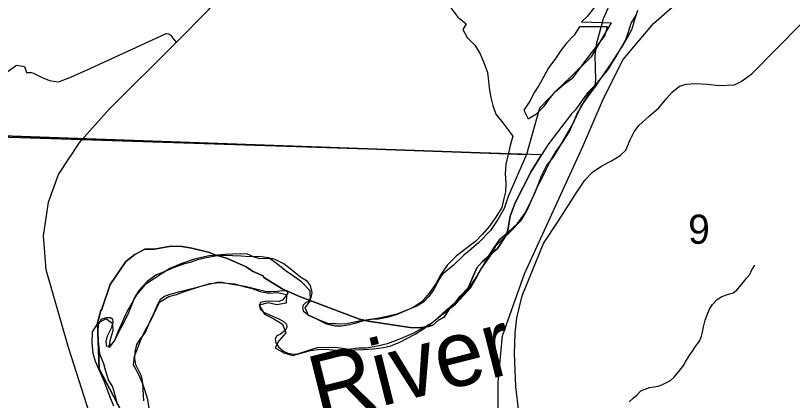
# Model space of a CAD drawing. Extents: x 0 to 34, y 0 to 22.
# Drawn here: x 3.401 to 4.521, y 19.391 to 19.945 of the extents above; entities that cross this region are included whole.
import ezdxf

# ---------------------------------------------------------------- set-up
doc = ezdxf.new("R2010")
doc.units = 0
for name, color, linetype in [('GM_X_County_Road', 7, 'Continuous'), ('GM_X_Major_River', 7, 'Continuous'), ('GM_X_Major_River_Text', 7, 'Continuous'), ('GM_X_Minor_River', 7, 'Continuous'), ('GM_X_Rail_Line', 7, 'Continuous'), ('GM_X_Section', 7, 'Continuous'), ('GM_X_Section_Text', 7, 'Continuous'), ('GM_X_State_Route', 7, 'Continuous')]:
    doc.layers.add(name, color=color, linetype=linetype)

msp = doc.modelspace()

# ---------------------------------------------------------------- linework, layer by layer
at = {"layer": 'GM_X_County_Road'}
for points in [[(4.1269, 19.3743), (4.1228, 19.4109), (4.1209, 19.4585), (4.1215, 19.4873), (4.1241, 19.5096), (4.1316, 19.5414), (4.1625, 19.6168), (4.1831, 19.648), (4.1986, 19.6722), (4.2087, 19.6877), (4.2222, 19.7082), (4.2333, 19.7195), (4.2467, 19.7285), (4.2605, 19.7358), (4.2728, 19.7436), (4.2811, 19.7514), (4.2876, 19.7662), (4.2934, 19.7777), (4.2999, 19.7869), (4.3149, 19.8001), (4.3287, 19.8121), (4.3404, 19.8258), (4.3481, 19.8347), (4.3586, 19.8432), (4.3683, 19.8464), (4.3814, 19.8472), (4.3986, 19.8461), (4.416, 19.8442), (4.4377, 19.8451), (4.4476, 19.85), (4.4628, 19.8611), (4.5336, 19.9326)], [(3.4971, 19.8633), (3.5036, 19.8663), (3.6177, 19.9188), (3.6193, 19.919), (3.6214, 19.9187), (3.6231, 19.9181), (3.6241, 19.9176), (3.6249, 19.9168), (3.6332, 19.9061)], [(3.3827, 19.8589), (3.403, 19.8734), (3.4146, 19.8714), (3.4172, 19.8628), (3.42, 19.863), (3.424, 19.863), (3.4275, 19.862), (3.4397, 19.8556), (3.4506, 19.8514), (3.4625, 19.8497), (3.4646, 19.8498), (3.4822, 19.8565), (3.4971, 19.8633)]]:
    msp.add_lwpolyline(points, dxfattribs=at)
at = {"layer": 'GM_X_Major_River'}
msp.add_line((4.2548, 19.9289), (4.2143, 19.9287), dxfattribs=at)
for points in [[(4.052, 20.1082), (4.0423, 20.1002), (4.0328, 20.1012), (4.0242, 20.0907), (4.0344, 20.0703), (4.0413, 20.0588), (4.0338, 20.0456), (4.027, 20.0325), (4.0207, 20.0186), (4.0136, 20.0085), (4.0167, 19.9966), (4.0214, 19.9828), (4.0245, 19.969), (4.0287, 19.956), (4.0391, 19.9425), (4.0508, 19.9329)], [(4.2901, 19.9259), (4.2942, 19.9394), (4.2986, 19.9526)], [(3.594, 19.3794), (3.5922, 19.392), (3.588, 19.4062), (3.5845, 19.4158), (3.5789, 19.4289), (3.5713, 19.4421), (3.5728, 19.4546), (3.5778, 19.4666), (3.5819, 19.4782), (3.588, 19.4906), (3.5969, 19.507), (3.6091, 19.5325), (3.6222, 19.5404), (3.6337, 19.5435), (3.6437, 19.5474), (3.6552, 19.5512), (3.6717, 19.5564), (3.6813, 19.5591), (3.6958, 19.5606), (3.7064, 19.5598), (3.717, 19.5588), (3.7305, 19.5549), (3.7426, 19.5519), (3.7542, 19.5477), (3.7667, 19.5454), (3.7792, 19.5462), (3.7921, 19.5435), (3.7917, 19.531), (3.7783, 19.5287), (3.7655, 19.5314), (3.7528, 19.528), (3.7604, 19.5152), (3.7739, 19.5084), (3.7862, 19.5007), (3.7911, 19.4881), (3.7809, 19.4766), (3.7756, 19.4665), (3.7883, 19.4593), (3.8011, 19.4554), (3.8145, 19.4592), (3.8268, 19.463), (3.8405, 19.4645), (3.8534, 19.4641), (3.8685, 19.4629), (3.8784, 19.4633), (3.8906, 19.4637), (3.9035, 19.464), (3.9176, 19.4651), (3.9317, 19.467), (3.9424, 19.4693), (3.9555, 19.475), (3.9655, 19.48), (3.9775, 19.4861), (3.9895, 19.4941), (3.9992, 19.5006), (4.0097, 19.5094), (4.0226, 19.5212), (4.0332, 19.5299), (4.0469, 19.5432), (4.0567, 19.5551), (4.0663, 19.5692), (4.0747, 19.5834), (4.0819, 19.5961), (4.0903, 19.6095), (4.0999, 19.6233), (4.1127, 19.6339), (4.1249, 19.6457), (4.1356, 19.6598), (4.1424, 19.6736), (4.1489, 19.6871), (4.1535, 19.698), (4.1603, 19.7103), (4.1664, 19.7234), (4.1721, 19.735), (4.1809, 19.7496), (4.1908, 19.7637), (4.1996, 19.7771), (4.2053, 19.7898), (4.2111, 19.8037), (4.2199, 19.8183), (4.2302, 19.8331), (4.2377, 19.8432), (4.2441, 19.8529), (4.2509, 19.8625), (4.2596, 19.8752), (4.268, 19.8882), (4.2764, 19.9009), (4.2836, 19.9136), (4.2901, 19.9259)], [(4.0508, 19.9329), (4.0462, 19.9251), (4.0523, 19.9135), (4.0634, 19.9022), (4.071, 19.8898), (4.077, 19.8759), (4.0819, 19.8628), (4.0834, 19.8506), (4.0843, 19.8411), (4.0868, 19.827), (4.0895, 19.8155), (4.0937, 19.8028), (4.1039, 19.7907), (4.1185, 19.7713)], [(4.2143, 19.9287), (4.2067, 19.9168), (4.1957, 19.905), (4.1874, 19.8946), (4.1787, 19.8819), (4.1699, 19.8697), (4.1631, 19.8573), (4.1559, 19.8443), (4.1495, 19.8346), (4.1426, 19.8215), (4.1342, 19.8088), (4.1403, 19.7965)], [(4.1403, 19.7965), (4.1526, 19.8033), (4.1639, 19.8151), (4.1723, 19.8266), (4.1802, 19.8362), (4.1927, 19.8469), (4.2051, 19.856), (4.215, 19.8686), (4.2225, 19.8794), (4.232, 19.892), (4.2415, 19.9035), (4.251, 19.9157), (4.2548, 19.9289)], [(4.1185, 19.7713), (4.1143, 19.7577), (4.1112, 19.743), (4.1082, 19.7309), (4.1073, 19.7169), (4.1081, 19.7043), (4.1077, 19.6914), (4.1055, 19.6816), (4.1024, 19.6684), (4.094, 19.6546), (4.0849, 19.6416), (4.0739, 19.6298), (4.0648, 19.6202), (4.0508, 19.6096), (4.0368, 19.5986), (4.0243, 19.5861), (4.0147, 19.5723), (4.0071, 19.5589), (3.9976, 19.5455), (3.9869, 19.5329), (3.9745, 19.5245), (3.9634, 19.5199), (3.9503, 19.5143), (3.9372, 19.5101), (3.9246, 19.5079), (3.9144, 19.5074), (3.9014, 19.5052), (3.8906, 19.5017), (3.8807, 19.499), (3.8711, 19.4977), (3.8617, 19.498), (3.8496, 19.5007), (3.8365, 19.5072), (3.8238, 19.5133), (3.8188, 19.5241), (3.8267, 19.5348), (3.8264, 19.5489), (3.8143, 19.5611), (3.8009, 19.5706), (3.7901, 19.5781), (3.7794, 19.5868), (3.7664, 19.596), (3.752, 19.5983), (3.7387, 19.5976), (3.7266, 19.5984), (3.7141, 19.5991), (3.7046, 19.5994), (3.6897, 19.5984), (3.6764, 19.5961), (3.6637, 19.5931), (3.653, 19.5896), (3.6434, 19.5869), (3.6288, 19.5816), (3.6192, 19.5774), (3.6038, 19.571), (3.591, 19.5619), (3.5796, 19.5497), (3.5736, 19.54), (3.5691, 19.5288), (3.5637, 19.516), (3.5568, 19.501), (3.5508, 19.4913), (3.5447, 19.4782), (3.5364, 19.4671), (3.5383, 19.4792), (3.5421, 19.4916), (3.5416, 19.5011), (3.5316, 19.5083), (3.5196, 19.5018), (3.512, 19.4895), (3.5115, 19.4736), (3.513, 19.4591), (3.5164, 19.4472), (3.5221, 19.4345), (3.5288, 19.4191), (3.5327, 19.4091), (3.5372, 19.396), (3.5429, 19.3829)]]:
    msp.add_lwpolyline(points, dxfattribs=at)
at = {"layer": 'GM_X_Minor_River'}
msp.add_lwpolyline([(4.2859, 19.3887), (4.2918, 19.3942), (4.2968, 19.3986), (4.3027, 19.4045), (4.3089, 19.4073), (4.3151, 19.4094), (4.3215, 19.4103), (4.328, 19.4116), (4.333, 19.4133), (4.3388, 19.4161), (4.3458, 19.4197), (4.3509, 19.4245), (4.3576, 19.4326), (4.3644, 19.4411), (4.3672, 19.4463), (4.3725, 19.4553), (4.3772, 19.4616), (4.3812, 19.4679), (4.3876, 19.476), (4.3901, 19.4835), (4.3915, 19.4892), (4.3929, 19.4967), (4.3955, 19.5062), (4.3992, 19.5163), (4.4025, 19.523), (4.4061, 19.529), (4.4128, 19.536), (4.4194, 19.5403), (4.4294, 19.5438), (4.436, 19.5458), (4.441, 19.5498), (4.445, 19.5546), (4.4509, 19.5613), (4.4549, 19.5668), (4.4597, 19.5724), (4.4621, 19.578), (4.4669, 19.5854)], dxfattribs=at)
at = {"layer": 'GM_X_Rail_Line'}
msp.add_lwpolyline([(4.0971, 19.3526), (4.0971, 19.4175), (4.1034, 19.4841), (4.1353, 19.5729), (4.219, 19.7566), (4.2492, 19.8256), (4.2772, 19.8815), (4.3213, 19.9337), (4.3834, 19.9889), (4.4557, 20.0732), (4.5053, 20.133), (4.6016, 20.2455), (4.6862, 20.3389), (4.7356, 20.3882), (4.8861, 20.5288), (4.9518, 20.5917), (4.997, 20.6442), (5.022, 20.6941), (5.048, 20.7585), (5.0622, 20.8479), (5.0705, 20.9)], dxfattribs=at)
at = {"layer": 'GM_X_Section'}
msp.add_lwpolyline([(3.1645, 20.7261), (4.3261, 20.699), (4.3194, 20.2817), (4.3193, 20.2753), (4.3164, 20.0605), (4.2362, 19.9572), (4.2253, 19.9438), (4.2171, 19.9357), (4.2598, 19.9346), (4.2313, 19.8855), (4.2007, 19.856), (4.1813, 19.8371), (4.1568, 19.8116), (4.1378, 19.745), (3.0048, 19.785)], close=True, dxfattribs=at)
for points in [[(3.5863, 19.3905), (3.585, 19.4156), (3.5829, 19.4258), (3.5797, 19.4327), (3.575, 19.4419), (3.5733, 19.4514), (3.574, 19.4609), (3.5761, 19.4715), (3.5808, 19.4782), (3.589, 19.489), (3.5951, 19.504), (3.6003, 19.5152), (3.6071, 19.5302), (3.6107, 19.5373), (3.6164, 19.541), (3.6256, 19.5445), (3.6386, 19.5476), (3.6725, 19.5563), (3.6919, 19.5611), (3.6987, 19.5609), (3.7138, 19.5583), (3.7327, 19.5556), (3.7459, 19.5522), (3.7636, 19.5476), (3.7693, 19.5475), (3.7791, 19.5484), (3.786, 19.549), (3.7917, 19.5488), (3.7935, 19.5469), (3.7934, 19.5442), (3.7911, 19.5413), (3.7868, 19.5357), (3.7814, 19.5335), (3.7644, 19.5339), (3.7545, 19.5319), (3.7525, 19.5278), (3.7539, 19.5221), (3.7591, 19.5178), (3.7711, 19.5126), (3.7801, 19.5086), (3.7872, 19.505), (3.792, 19.5007), (3.7926, 19.4958), (3.791, 19.4928), (3.788, 19.4902), (3.7833, 19.4865), (3.7783, 19.484), (3.7756, 19.4795), (3.7769, 19.4738), (3.7806, 19.468), (3.7876, 19.4618), (3.794, 19.459), (3.7997, 19.4581), (3.8053, 19.4576), (3.8114, 19.4589), (3.8256, 19.4635), (3.8366, 19.467), (3.8495, 19.4675), (3.8654, 19.4671), (3.8764, 19.4657), (3.8809, 19.4648), (3.8957, 19.4667), (3.9067, 19.4665), (3.9185, 19.4685), (3.9376, 19.4729), (3.9567, 19.48), (3.9754, 19.4883), (4.0015, 19.5024), (4.0185, 19.516), (4.0355, 19.5296), (4.0476, 19.5422), (4.0577, 19.5533), (4.0656, 19.5668), (4.0716, 19.5788), (4.0837, 19.5959), (4.0892, 19.6037), (4.0944, 19.6138), (4.0995, 19.6194), (4.1146, 19.6338), (4.1301, 19.6497), (4.1388, 19.6646), (4.1517, 19.6939), (4.1601, 19.7153), (4.1669, 19.7284), (4.1763, 19.7406), (4.1842, 19.7533), (4.2047, 19.7888), (4.2159, 19.8124), (4.2297, 19.8352), (4.2426, 19.8515), (4.2547, 19.866), (4.2673, 19.8858), (4.2808, 19.909), (4.2849, 19.9214), (4.289, 19.9339), (4.2969, 19.947)], [(3.0048, 19.785), (4.1378, 19.745), (4.1117, 19.6846), (4.1056, 19.667), (4.0968, 19.6513), (4.0862, 19.6356), (4.0695, 19.6182), (4.0583, 19.6086), (4.0475, 19.6002), (4.0323, 19.585), (4.0165, 19.5721), (4.0114, 19.5647), (4.0046, 19.5508), (3.9972, 19.5404), (3.9901, 19.5326), (3.9798, 19.5268), (3.9496, 19.5147), (3.9256, 19.5092), (3.8967, 19.505), (3.8761, 19.5009), (3.8636, 19.5012), (3.853, 19.5011), (3.838, 19.5068), (3.823, 19.5143), (3.8171, 19.5186), (3.8157, 19.524), (3.8165, 19.5285), (3.82, 19.5318), (3.8242, 19.534), (3.8274, 19.5389), (3.8291, 19.5464), (3.8267, 19.5563), (3.8223, 19.5621), (3.8122, 19.5684), (3.7992, 19.5789), (3.788, 19.5875), (3.7776, 19.5927), (3.7727, 19.5947), (3.7613, 19.595), (3.7534, 19.5948), (3.7447, 19.5977), (3.7357, 19.6013), (3.7259, 19.6019), (3.7035, 19.601), (3.6804, 19.5989), (3.6609, 19.5948), (3.6395, 19.5874), (3.6238, 19.5809), (3.6019, 19.5663), (3.588, 19.5572), (3.5763, 19.5434), (3.5621, 19.5184), (3.5493, 19.4907), (3.5436, 19.4757), (3.5394, 19.4716), (3.5355, 19.469), (3.5329, 19.4687), (3.5325, 19.4714), (3.5319, 19.4759), (3.534, 19.4839), (3.5403, 19.4962), (3.542, 19.5034), (3.5417, 19.5075), (3.5384, 19.5099), (3.5323, 19.51), (3.5243, 19.5072), (3.5207, 19.499), (3.5196, 19.485), (3.5227, 19.458), (3.5285, 19.4442), (3.5309, 19.4347), (3.5354, 19.4198), (3.5413, 19.4106), (3.5427, 19.4056), (3.5458, 19.3934), (3.5479, 19.3846)]]:
    msp.add_lwpolyline(points, dxfattribs=at)
at = {"layer": 'GM_X_State_Route'}
for points in [[(3.6332, 19.9061), (3.6794, 19.9534), (3.7523, 20.0363), (3.8132, 20.1061), (3.8426, 20.1329), (4, 20.2944), (4.0187, 20.3121), (4.088, 20.3587), (4.1525, 20.3983), (4.3383, 20.5193), (4.4127, 20.568), (4.5454, 20.6702), (4.7265, 20.8124), (4.8353, 20.9)], [(4.2573, 19.9596), (4.2485, 19.94), (4.2386, 19.9034), (4.2364, 19.8871), (4.2376, 19.8529), (4.2363, 19.8445), (4.2258, 19.8337), (4.2082, 19.8086), (4.2027, 19.8034), (4.1703, 19.7608), (4.1595, 19.7445), (4.1448, 19.7203), (4.1215, 19.6752), (4.1146, 19.6563), (4.1112, 19.6359), (4.1073, 19.6265), (4.0963, 19.6096), (4.0743, 19.5903), (4.0665, 19.5818), (4.0537, 19.5528), (4.0425, 19.5412), (4.0347, 19.5308), (4.0289, 19.5263), (4.0194, 19.5109), (4.011, 19.5062), (4.0029, 19.4991), (3.9971, 19.4973), (3.9834, 19.4953), (3.9702, 19.496), (3.9097, 19.5049), (3.8972, 19.5078), (3.8106, 19.5405), (3.7858, 19.5516), (3.7596, 19.5678), (3.7585, 19.5701), (3.7438, 19.5765), (3.733, 19.5835), (3.7055, 19.5959), (3.6871, 19.6008), (3.6811, 19.604), (3.6558, 19.6103), (3.6414, 19.6125), (3.6255, 19.6128), (3.6018, 19.6087), (3.5878, 19.6087), (3.5732, 19.601), (3.5605, 19.591), (3.5378, 19.558), (3.526, 19.5222), (3.5244, 19.5205), (3.5194, 19.5024), (3.5218, 19.4362), (3.5528, 19.3778)], [(3.8721, 18.5552), (3.8591, 18.5787), (3.7642, 18.7547), (3.7054, 18.8591), (3.6739, 18.9159), (3.6649, 18.9324), (3.6413, 18.9804), (3.6128, 19.0415), (3.5458, 19.2539), (3.478, 19.467), (3.4454, 19.579), (3.4417, 19.628), (3.4489, 19.6761), (3.4634, 19.716), (3.493, 19.7613), (3.4966, 19.7654), (3.5366, 19.81), (3.6332, 19.9061)], [(3.5528, 19.3778), (3.5218, 19.4362), (3.5194, 19.5024), (3.5244, 19.5205), (3.526, 19.5222), (3.5378, 19.558), (3.5605, 19.591), (3.5732, 19.601), (3.5878, 19.6087), (3.6018, 19.6087), (3.6255, 19.6128), (3.6414, 19.6125), (3.6558, 19.6103), (3.6811, 19.604), (3.6871, 19.6008), (3.7055, 19.5959), (3.733, 19.5835), (3.7438, 19.5765), (3.7585, 19.5701), (3.7596, 19.5678), (3.7858, 19.5516), (3.8106, 19.5405), (3.8972, 19.5078), (3.9097, 19.5049), (3.9702, 19.496), (3.9834, 19.4953), (3.9971, 19.4973), (4.0029, 19.4991), (4.011, 19.5062), (4.0194, 19.5109), (4.0289, 19.5263), (4.0347, 19.5308), (4.0425, 19.5412), (4.0537, 19.5528), (4.0665, 19.5818), (4.0743, 19.5903), (4.0963, 19.6096), (4.1073, 19.6265), (4.1112, 19.6359), (4.1146, 19.6563), (4.1215, 19.6752), (4.1448, 19.7203), (4.1595, 19.7445), (3.4964, 19.7659), (3.3482, 19.7707)]]:
    msp.add_lwpolyline(points, dxfattribs=at)

# ---------------------------------------------------------------- texts
at = {"layer": 'GM_X_Major_River_Text'}
msp.add_text('River', height=0.0947, rotation=14.1362, dxfattribs=at).set_placement((3.8391, 19.3597))
at = {"layer": 'GM_X_Section_Text'}
msp.add_text('9', height=0.0419, rotation=0, dxfattribs=at).set_placement((4.3711, 19.6164))

doc.saveas('drawing.dxf')
